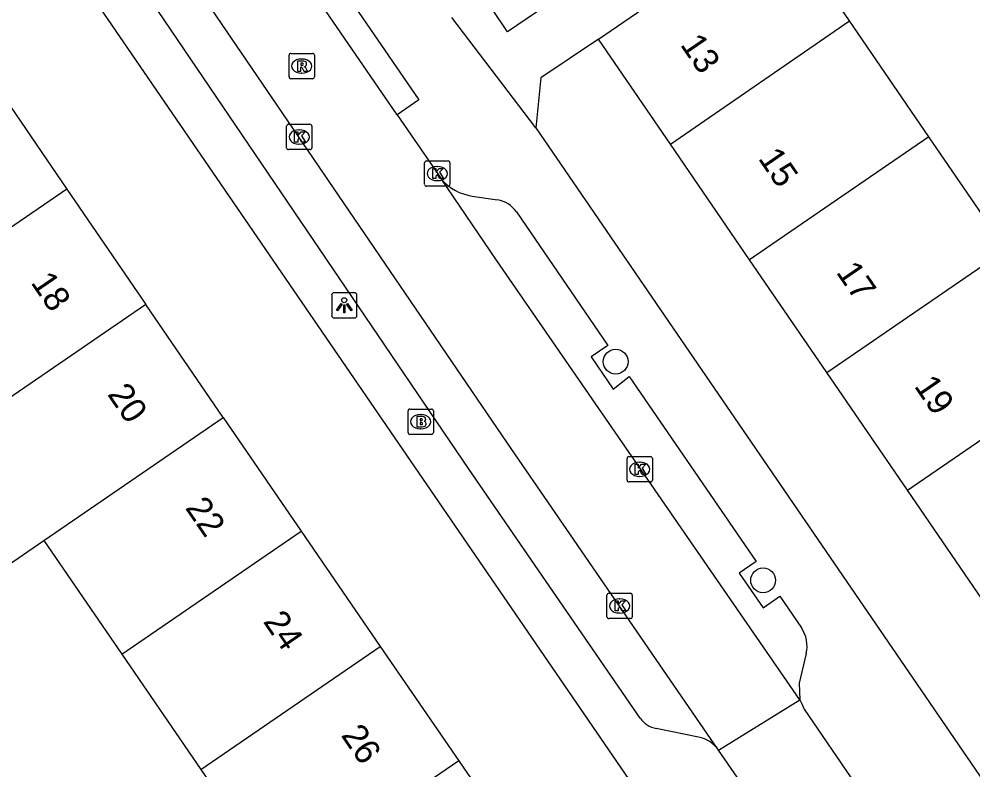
# Model space of a CAD drawing. Extents: x 157466 to 158888, y 383063 to 384677.
# Drawn here: x 158131.78 to 158169.45, y 383810.57 to 383840.23 of the extents above; entities that cross this region are included whole.
import ezdxf

# ---------------------------------------------------------------- set-up
doc = ezdxf.new("R2010")
doc.units = 0
for name, color, linetype in [('IMGEO_Boom', 7, 'Continuous'), ('IMGEO_Brandkraan', 7, 'Continuous'), ('IMGEO_Kolk', 7, 'Continuous'), ('IMGEO_Lichtpunt', 7, 'Continuous'), ('IMGEO_Pand', 7, 'Continuous'), ('IMGEO_Pand_nummerreeks', 7, 'Continuous'), ('IMGEO_Rijbaan_lokaal_open', 7, 'Continuous'), ('IMGEO_Rioolput', 7, 'Continuous'), ('IMGEO_Voetpad_open', 7, 'Continuous')]:
    doc.layers.add(name, color=color, linetype=linetype)

msp = doc.modelspace()

# ---------------------------------------------------------------- linework, layer by layer
at = {"layer": 'IMGEO_Boom'}
for centre in [(158155.34, 383826.697), (158161.164, 383818.06)]:
    msp.add_circle(centre, 0.489, dxfattribs=at)
at = {"layer": 'IMGEO_Brandkraan'}
for p, q in [((158147.142, 383823.899), (158147.142, 383824.751)), ((158147.217, 383824.825), (158148.069, 383824.825)), ((158148.143, 383824.751), (158148.143, 383823.899)), ((158147.63, 383824.605), (158147.655, 383824.605)), ((158147.653, 383824.045), (158147.628, 383824.045)), ((158148.069, 383823.825), (158147.217, 383823.825))]:
    msp.add_line(p, q, dxfattribs=at)
for points in [[(158147.142, 383823.899), (158147.142, 383824.751)], [(158147.217, 383824.825), (158148.069, 383824.825)], [(158148.143, 383824.751), (158148.143, 383823.899)], [(158147.49, 383824.525), (158147.49, 383824.125), (158147.703, 383824.125)], [(158147.721, 383824.525), (158147.49, 383824.525)], [(158147.669, 383824.444), (158147.615, 383824.444), (158147.615, 383824.368)], [(158147.615, 383824.368), (158147.668, 383824.368)], [(158147.677, 383824.292), (158147.615, 383824.292), (158147.615, 383824.211)], [(158147.615, 383824.211), (158147.677, 383824.211)], [(158148.069, 383823.825), (158147.217, 383823.825)]]:
    msp.add_lwpolyline(points, dxfattribs=at)
for centre, radius, start, end in [((158147.219, 383824.749), 0.0765, 91.552, 178.448), ((158147.219, 383824.749), 0.0765, 91.552, 178.448), ((158148.067, 383824.749), 0.0765, 1.552, 88.448), ((158148.067, 383824.749), 0.0765, 1.552, 88.448), ((158147.67, 383824.406), 0.0379, 267.8285, 90.9355), ((158147.678, 383824.251), 0.0404, 269.8759, 90.5077), ((158147.725, 383824.38), 0.145, 59.4692, 91.5367), ((158147.75, 383824.427), 0.0922, 285.5137, 58.1501), ((158147.755, 383824.235), 0.105, 301.3115, 78.989), ((158147.219, 383823.901), 0.0765, 181.552, 268.448), ((158147.219, 383823.901), 0.0765, 181.552, 268.448), ((158147.709, 383824.376), 0.251, 268.6676, 293.5347), ((158148.067, 383823.901), 0.0765, 271.552, 358.448), ((158148.067, 383823.901), 0.0765, 271.552, 358.448)]:
    msp.add_arc(centre, radius, start, end, dxfattribs=at)
for centre, major_axis, ratio, start_param, end_param in [((158147.629, 383824.325), (-0.387, 0.002), 0.722429, 4.712389, 7.853982), ((158147.654, 383824.325), (-0.39, 0.002), 0.717154, 1.570796, 4.712389)]:
    msp.add_ellipse(centre, major_axis=major_axis, ratio=ratio, start_param=start_param, end_param=end_param, dxfattribs=at)
at = {"layer": 'IMGEO_Kolk'}
for p, q in [((158142.343, 383835.144), (158142.343, 383835.996)), ((158142.418, 383836.07), (158143.27, 383836.07)), ((158143.344, 383835.996), (158143.344, 383835.144)), ((158142.831, 383835.85), (158142.856, 383835.85)), ((158142.854, 383835.29), (158142.829, 383835.29)), ((158143.27, 383835.07), (158142.418, 383835.07)), ((158147.794, 383833.7), (158147.794, 383834.552)), ((158147.869, 383834.626), (158148.721, 383834.626)), ((158148.795, 383834.552), (158148.795, 383833.7)), ((158148.282, 383834.406), (158148.307, 383834.406)), ((158148.305, 383833.846), (158148.28, 383833.846)), ((158148.721, 383833.626), (158147.869, 383833.626)), ((158155.791, 383822.02), (158155.791, 383822.872)), ((158155.866, 383822.946), (158156.718, 383822.946)), ((158156.792, 383822.872), (158156.792, 383822.02)), ((158156.279, 383822.726), (158156.304, 383822.726)), ((158156.302, 383822.166), (158156.277, 383822.166)), ((158156.718, 383821.946), (158155.866, 383821.946)), ((158154.995, 383816.623), (158154.995, 383817.475)), ((158155.07, 383817.549), (158155.922, 383817.549)), ((158155.996, 383817.475), (158155.996, 383816.623)), ((158155.483, 383817.329), (158155.508, 383817.329)), ((158155.506, 383816.769), (158155.481, 383816.769)), ((158155.922, 383816.549), (158155.07, 383816.549))]:
    msp.add_line(p, q, dxfattribs=at)
for points in [[(158142.343, 383835.144), (158142.343, 383835.996)], [(158142.418, 383836.07), (158143.27, 383836.07)], [(158143.344, 383835.996), (158143.344, 383835.144)], [(158142.664, 383835.77), (158142.787, 383835.77), (158142.787, 383835.619), (158142.917, 383835.77), (158143.081, 383835.77), (158142.935, 383835.619), (158143.088, 383835.37), (158142.936, 383835.37), (158142.851, 383835.534), (158142.787, 383835.467), (158142.787, 383835.37), (158142.664, 383835.37), (158142.664, 383835.77)], [(158143.27, 383835.07), (158142.418, 383835.07)], [(158147.794, 383833.7), (158147.794, 383834.552)], [(158147.869, 383834.626), (158148.721, 383834.626)], [(158148.795, 383834.552), (158148.795, 383833.7)], [(158148.115, 383834.326), (158148.238, 383834.326), (158148.238, 383834.175), (158148.368, 383834.326), (158148.532, 383834.326), (158148.386, 383834.175), (158148.539, 383833.926), (158148.387, 383833.926), (158148.302, 383834.09), (158148.238, 383834.023), (158148.238, 383833.926), (158148.115, 383833.926), (158148.115, 383834.326)], [(158148.721, 383833.626), (158147.869, 383833.626)], [(158155.791, 383822.02), (158155.791, 383822.872)], [(158155.866, 383822.946), (158156.718, 383822.946)], [(158156.792, 383822.872), (158156.792, 383822.02)], [(158156.112, 383822.646), (158156.235, 383822.646), (158156.235, 383822.495), (158156.365, 383822.646), (158156.529, 383822.646), (158156.383, 383822.495), (158156.536, 383822.246), (158156.384, 383822.246), (158156.299, 383822.41), (158156.235, 383822.343), (158156.235, 383822.246), (158156.112, 383822.246), (158156.112, 383822.646)], [(158156.718, 383821.946), (158155.866, 383821.946)], [(158154.995, 383816.623), (158154.995, 383817.475)], [(158155.07, 383817.549), (158155.922, 383817.549)], [(158155.996, 383817.475), (158155.996, 383816.623)], [(158155.316, 383817.249), (158155.439, 383817.249), (158155.439, 383817.098), (158155.569, 383817.249), (158155.733, 383817.249), (158155.587, 383817.098), (158155.74, 383816.849), (158155.588, 383816.849), (158155.503, 383817.013), (158155.439, 383816.946), (158155.439, 383816.849), (158155.316, 383816.849), (158155.316, 383817.249)], [(158155.922, 383816.549), (158155.07, 383816.549)]]:
    msp.add_lwpolyline(points, dxfattribs=at)
for centre, start, end in [((158142.42, 383835.994), 91.552, 178.448), ((158142.42, 383835.994), 91.552, 178.448), ((158143.268, 383835.994), 1.552, 88.448), ((158143.268, 383835.994), 1.552, 88.448), ((158142.42, 383835.146), 181.552, 268.448), ((158142.42, 383835.146), 181.552, 268.448), ((158143.268, 383835.146), 271.552, 358.448), ((158143.268, 383835.146), 271.552, 358.448), ((158147.871, 383834.55), 91.552, 178.448), ((158147.871, 383834.55), 91.552, 178.448), ((158148.719, 383834.55), 1.552, 88.448), ((158148.719, 383834.55), 1.552, 88.448), ((158147.871, 383833.702), 181.552, 268.448), ((158147.871, 383833.702), 181.552, 268.448), ((158148.719, 383833.702), 271.552, 358.448), ((158148.719, 383833.702), 271.552, 358.448), ((158155.868, 383822.87), 91.552, 178.448), ((158155.868, 383822.87), 91.552, 178.448), ((158156.716, 383822.87), 1.552, 88.448), ((158156.716, 383822.87), 1.552, 88.448), ((158155.868, 383822.022), 181.552, 268.448), ((158155.868, 383822.022), 181.552, 268.448), ((158156.716, 383822.022), 271.552, 358.448), ((158156.716, 383822.022), 271.552, 358.448), ((158155.072, 383817.473), 91.552, 178.448), ((158155.072, 383817.473), 91.552, 178.448), ((158155.92, 383817.473), 1.552, 88.448), ((158155.92, 383817.473), 1.552, 88.448), ((158155.072, 383816.625), 181.552, 268.448), ((158155.072, 383816.625), 181.552, 268.448), ((158155.92, 383816.625), 271.552, 358.448), ((158155.92, 383816.625), 271.552, 358.448)]:
    msp.add_arc(centre, 0.0765, start, end, dxfattribs=at)
for centre, major_axis, ratio, start_param, end_param in [((158142.83, 383835.57), (-0.387, 0.002), 0.722429, 4.712389, 7.853982), ((158142.855, 383835.57), (-0.39, 0.002), 0.717154, 1.570796, 4.712389), ((158148.281, 383834.126), (-0.387, 0.002), 0.722429, 4.712389, 7.853982), ((158148.306, 383834.126), (-0.39, 0.002), 0.717154, 1.570796, 4.712389), ((158156.278, 383822.446), (-0.387, 0.002), 0.722429, 4.712389, 7.853982), ((158156.303, 383822.446), (-0.39, 0.002), 0.717154, 1.570796, 4.712389), ((158155.482, 383817.049), (-0.387, 0.002), 0.722429, 4.712389, 7.853982), ((158155.507, 383817.049), (-0.39, 0.002), 0.717154, 1.570796, 4.712389)]:
    msp.add_ellipse(centre, major_axis=major_axis, ratio=ratio, start_param=start_param, end_param=end_param, dxfattribs=at)
at = {"layer": 'IMGEO_Lichtpunt'}
for p, q in [((158144.126, 383829.325), (158144.126, 383828.518)), ((158144.126, 383829.325), (158144.126, 383828.518)), ((158145.028, 383829.42), (158144.22, 383829.42)), ((158145.028, 383829.42), (158144.22, 383829.42)), ((158145.122, 383828.518), (158145.122, 383829.325)), ((158145.122, 383828.518), (158145.122, 383829.325)), ((158144.22, 383828.424), (158145.028, 383828.424)), ((158144.22, 383828.424), (158145.028, 383828.424))]:
    msp.add_line(p, q, dxfattribs=at)
for points in [[(158144.5, 383828.989), (158144.539, 383828.961), (158144.351, 383828.699), (158144.313, 383828.726), (158144.5, 383828.989)], [(158144.602, 383828.941), (158144.649, 383828.941), (158144.649, 383828.619), (158144.602, 383828.619), (158144.602, 383828.941)], [(158144.712, 383828.961), (158144.75, 383828.988), (158144.937, 383828.726), (158144.898, 383828.698), (158144.712, 383828.961)]]:
    msp.add_lwpolyline(points, dxfattribs=at)
msp.add_circle((158144.625, 383829.123), 0.0994, dxfattribs=at)
for centre, start, end in [((158144.22, 383829.325), 90, 180), ((158144.22, 383829.325), 90, 180), ((158145.028, 383829.325), 0, 90), ((158145.028, 383829.325), 0, 90), ((158144.22, 383828.518), 180, 270), ((158144.22, 383828.518), 180, 270), ((158145.028, 383828.518), 270, 0), ((158145.028, 383828.518), 270, 360)]:
    msp.add_arc(centre, 0.0946, start, end, dxfattribs=at)
at = {"layer": 'IMGEO_Pand'}
for points in [[(158154.662, 383839.435), (158161.747, 383844.288)], [(158164.573, 383840.163), (158161.747, 383844.288)], [(158157.502, 383835.289), (158164.573, 383840.163)], [(158167.715, 383835.576), (158164.573, 383840.163)], [(158157.502, 383835.289), (158154.662, 383839.435)], [(158130.633, 383837.936), (158133.663, 383833.515)], [(158167.715, 383835.576), (158160.63, 383830.722)], [(158170.767, 383831.121), (158167.715, 383835.576)], [(158160.63, 383830.722), (158157.502, 383835.289)], [(158133.663, 383833.515), (158126.572, 383828.656)], [(158133.663, 383833.515), (158136.787, 383828.957)], [(158163.682, 383826.267), (158170.767, 383831.121)], [(158163.682, 383826.267), (158160.63, 383830.722)], [(158136.787, 383828.957), (158129.696, 383824.098)], [(158139.847, 383824.491), (158136.787, 383828.957)], [(158166.865, 383821.62), (158163.682, 383826.267)], [(158166.865, 383821.62), (158173.95, 383826.474)], [(158132.756, 383819.632), (158139.847, 383824.491)], [(158139.847, 383824.491), (158142.925, 383820)], [(158129.696, 383824.098), (158126.4, 383821.839), (158126.671, 383821.444), (158129.46, 383817.373), (158132.756, 383819.632)], [(158170.006, 383817.035), (158166.865, 383821.62)], [(158135.834, 383815.141), (158142.925, 383820)], [(158142.925, 383820), (158146.045, 383815.447)], [(158132.756, 383819.632), (158135.834, 383815.141)], [(158138.954, 383810.588), (158146.045, 383815.447)], [(158146.045, 383815.447), (158149.143, 383810.927)], [(158135.834, 383815.141), (158138.954, 383810.588)], [(158149.143, 383810.927), (158142.052, 383806.068)], [(158149.143, 383810.927), (158152.262, 383806.376)], [(158138.954, 383810.588), (158142.052, 383806.068)]]:
    msp.add_lwpolyline(points, dxfattribs=at)
at = {"layer": 'IMGEO_Rijbaan_lokaal_open'}
for points in [[(158159.408, 383811.358), (158151.075, 383823.483), (158125.645, 383860.78)], [(158146.706, 383836.446), (158142.267, 383842.936)], [(158146.706, 383836.446), (158148.464, 383833.901)], [(158162.61, 383813.344), (158150.635, 383830.702), (158148.464, 383833.901)], [(158159.408, 383811.358), (158162.61, 383813.344)], [(158162.61, 383813.344), (158162.677, 383813.202), (158162.787, 383812.969), (158164.805, 383810.025)], [(158161.728, 383807.983), (158159.408, 383811.358)]]:
    msp.add_lwpolyline(points, dxfattribs=at)
at = {"layer": 'IMGEO_Rioolput'}
for p, q in [((158142.441, 383837.944), (158142.441, 383838.796)), ((158142.516, 383838.87), (158143.368, 383838.87)), ((158142.929, 383838.65), (158142.954, 383838.65)), ((158143.442, 383838.796), (158143.442, 383837.944)), ((158143.368, 383837.87), (158142.516, 383837.87)), ((158142.952, 383838.09), (158142.927, 383838.09))]:
    msp.add_line(p, q, dxfattribs=at)
for points in [[(158142.441, 383837.944), (158142.441, 383838.796)], [(158142.516, 383838.87), (158143.368, 383838.87)], [(158143.03, 383838.568), (158142.778, 383838.57), (158142.778, 383838.17)], [(158143.442, 383838.796), (158143.442, 383837.944)], [(158142.778, 383838.17), (158142.902, 383838.17), (158142.902, 383838.332), (158142.913, 383838.332)], [(158142.956, 383838.489), (158142.902, 383838.489), (158142.902, 383838.408)], [(158142.902, 383838.408), (158142.954, 383838.408)], [(158142.96, 383838.303), (158143.031, 383838.17), (158143.171, 383838.17), (158143.106, 383838.296)], [(158143.368, 383837.87), (158142.516, 383837.87)]]:
    msp.add_lwpolyline(points, dxfattribs=at)
for centre, radius, start, end in [((158142.518, 383838.794), 0.0765, 91.552, 178.448), ((158142.518, 383838.794), 0.0765, 91.552, 178.448), ((158143.029, 383838.458), 0.109, 350.3612, 89.416), ((158143.366, 383838.794), 0.0765, 1.552, 88.448), ((158143.366, 383838.794), 0.0765, 1.552, 88.448), ((158142.912, 383838.279), 0.0533, 26.0293, 88.6989), ((158142.938, 383838.597), 0.19, 274.7715, 282.9687), ((158142.962, 383838.393), 0.0964, 77.0061, 93.1865), ((158142.976, 383838.45), 0.0378, 276.6634, 79.6772), ((158143.027, 383838.458), 0.112, 277.5842, 350.9817), ((158143.011, 383838.243), 0.108, 29.5134, 73.7905), ((158142.518, 383837.946), 0.0765, 181.552, 268.448), ((158142.518, 383837.946), 0.0765, 181.552, 268.448), ((158143.366, 383837.946), 0.0765, 271.552, 358.448), ((158143.366, 383837.946), 0.0765, 271.552, 358.448)]:
    msp.add_arc(centre, radius, start, end, dxfattribs=at)
for centre, major_axis, ratio, start_param, end_param in [((158142.928, 383838.37), (-0.387, 0.002), 0.722429, 4.712389, 7.853982), ((158142.953, 383838.37), (-0.39, 0.002), 0.717154, 1.570796, 4.712389)]:
    msp.add_ellipse(centre, major_axis=major_axis, ratio=ratio, start_param=start_param, end_param=end_param, dxfattribs=at)
at = {"layer": 'IMGEO_Voetpad_open'}
for points in [[(158113.406, 383872.129), (158156.487, 383809.272)], [(158156.312, 383812.618), (158149.56, 383822.442), (158125.726, 383857.567)], [(158155.802, 383844.282), (158156.425, 383843.367), (158151.072, 383839.723), (158150.449, 383840.639)], [(158142.267, 383842.936), (158143.125, 383843.523), (158147.564, 383837.033), (158146.706, 383836.446)], [(158152.194, 383835.929), (158148.872, 383840.291)], [(158154.662, 383839.435), (158152.39, 383837.906), (158152.194, 383835.929)], [(158152.194, 383835.929), (158182.143, 383792.209)], [(158149.674, 383833.235), (158150.677, 383833.084)], [(158151.42, 383832.618), (158155.037, 383827.34), (158154.368, 383826.882), (158155.238, 383825.612), (158155.876, 383826.115), (158160.889, 383818.801), (158160.22, 383818.343), (158161.16, 383816.971), (158161.828, 383817.429), (158162.683, 383816.182)], [(158162.865, 383815.172), (158162.593, 383813.995), (158162.61, 383813.344)], [(158158.61, 383811.87), (158156.94, 383812.204)]]:
    msp.add_lwpolyline(points, dxfattribs=at)
for centre, radius, start, end in [((158149.974, 383835.212), 1.999, 220.9627, 261.3793), ((158150.511, 383831.994), 1.102, 34.4576, 81.3516), ((158161.6, 383815.466), 1.298, 346.9314, 33.4985), ((158157.14, 383813.19), 1.006, 214.6526, 258.5588), ((158158.352, 383810.589), 1.306, 36.0394, 78.5918)]:
    msp.add_arc(centre, radius, start, end, dxfattribs=at)

# ---------------------------------------------------------------- texts
at = {"layer": 'IMGEO_Pand_nummerreeks'}
for s, rotation, p in [('13', 304.4113, (158157.865, 383839.218)), ('15', 304.4113, (158160.945, 383834.722)), ('17', 304.4113, (158164.024, 383830.227)), ('18', 304.4239, (158132.218, 383829.82)), ('20', 304.4231, (158135.244, 383825.406)), ('19', 304.4113, (158167.104, 383825.731)), ('22', 304.4239, (158138.317, 383820.921)), ('24', 304.4239, (158141.396, 383816.428)), ('26', 304.4239, (158144.473, 383811.938))]:
    msp.add_text(s, height=1, rotation=rotation, dxfattribs=at).set_placement(p)

doc.saveas('drawing.dxf')
